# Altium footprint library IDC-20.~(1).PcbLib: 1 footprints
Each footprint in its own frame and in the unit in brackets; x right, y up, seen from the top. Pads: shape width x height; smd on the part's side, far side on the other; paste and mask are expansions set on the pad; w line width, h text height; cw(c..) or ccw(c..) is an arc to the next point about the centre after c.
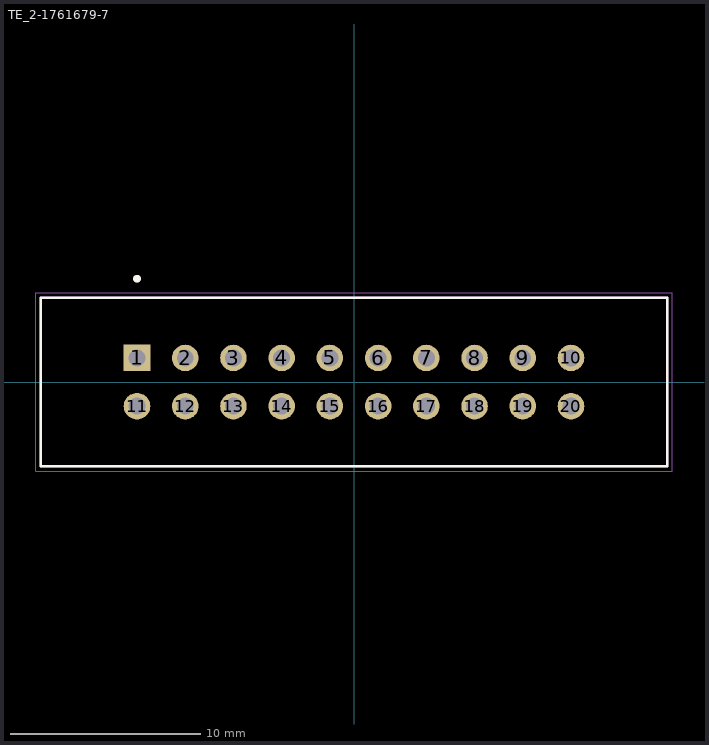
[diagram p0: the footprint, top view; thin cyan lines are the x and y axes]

## TE_2-1761679-7 [mm]
pads (20):
  rect 1.398x1.398 hole 0.89: 1(-11.43,1.27)
  round 1.398 hole 0.89: 2(-8.89,1.27) 3(-6.35,1.27) 4(-3.81,1.27) 5(-1.27,1.27) 6(1.27,1.27) 7(3.81,1.27) 8(6.35,1.27) 9(8.89,1.27) 10(11.43,1.27) 11(-11.43,-1.27) 12(-8.89,-1.27) 13(-6.35,-1.27) 14(-3.81,-1.27) 15(-1.27,-1.27) 16(1.27,-1.27) 17(3.81,-1.27) 18(6.35,-1.27) 19(8.89,-1.27) 20(11.43,-1.27)
Top Overlay:
  circle w0.2: c-11.43,5.445 r0.1
  lines w0.127: -16.51,-4.445 -16.51,4.445 16.51,4.445 16.51,-4.445 -16.51,-4.445
Mechanical 13:
  circle w0.2: c-11.43,5.445 r0.1
  lines w0.127: -16.51,-4.445 -16.51,4.445 16.51,4.445 16.51,-4.445 -16.51,-4.445
Mechanical 15:
  lines w0.05: -16.76,-4.695 16.76,-4.695 16.76,4.695 -16.76,4.695 -16.76,-4.695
